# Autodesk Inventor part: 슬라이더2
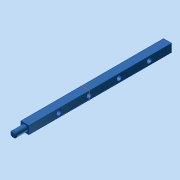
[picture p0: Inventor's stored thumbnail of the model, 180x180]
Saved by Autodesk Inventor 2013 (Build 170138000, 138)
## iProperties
Company: 한국ATC센터
Created: 2015-04
Part Number: 슬라이더2
Document SubType Name: Modeling
Designer: KYOUNG IL JANG
Density: 7.85 g/cm^3
Material: 강
Author: KYOUNG IL JANG
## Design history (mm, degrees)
sketch "스케치3"
  geometry: L1 (4, 142)-(-4, 142); L2 (-4, 142)-(-4, 0); L3 (-4, 0)-(4, 0); L4 (4, 0)-(4, 142); 3 further points
  constraints: 8 end point, 2 coincident, 2 parallel, 1 horizontal, 1 midpoint, 1 perpendicular
  dimensions: "d5" = 8 distance of L1.start L1.end; "d6" = 142 distance of L1.end L2.end
extrude "돌출3" new body sketch "스케치3" stored distance "d7" = 8; taper "d8" = 0 deg
sketch "스케치4"
  geometry: L1 (8, 0)-(0, 0) reference; 3 further points
  constraints: 1 midpoint, 1 vertical alignment
  dimensions: "d9" = 30 distance of point (4, 30) point (4, 0)
hole "구멍1" sketch "스케치4" at (4, 30) diameter "d10" = 5; stored, may be unused: countersink angle "d14" = 90 deg, drill point angle "d16" = 118 deg; dims "d11" = 6, "d12" = 4, "d13" = 2, "d15" = 8
sketch "스케치5"
  geometry: C1 r 3 at (4, -4); 1 further point
  constraints: 1 centre point, 1 coincident
  dimensions: "d20" = 6 diameter of C1
extrude "돌출4" join sketch "스케치5" distance "d21" = 12; taper "d22" = 0 deg
chamfer "모따기1" distance "d23" = 1; stored, may be unused: second distance "d24" = 2, angle "d25" = 45 deg
node "작업 평면2"
  node "작업축1"
node "솔리드1"
pattern_linear "직사각형 패턴1" dims "d19" = 30
node "솔리드2"
other parameters: "d26" = 0
